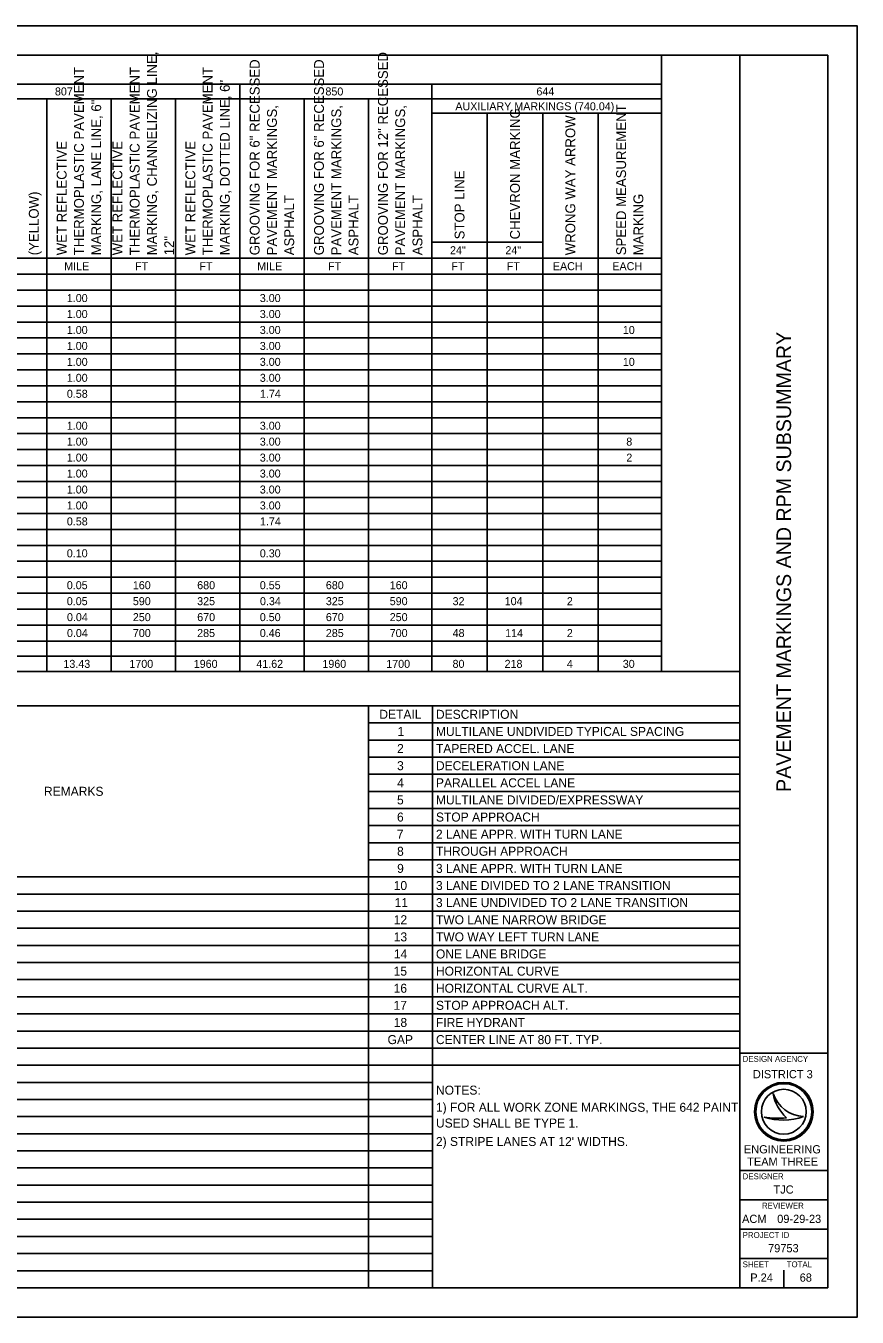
# Model space of a CAD drawing. Extents: x 0 to 34, y 0 to 22.
# Drawn here: x 19.84 to 34, y 0 to 22 of the extents above; entities that cross this region are included whole.
import ezdxf

# ---------------------------------------------------------------- set-up
doc = ezdxf.new("R2010")
doc.units = 0
for name, color, linetype in [('SH_Border', 7, 'Continuous'), ('SH_Cut_Line', 7, 'Continuous'), ('SH_Data', 7, 'Continuous'), ('SH_Text', 7, 'Continuous')]:
    doc.layers.add(name, color=color, linetype=linetype)

msp = doc.modelspace()

# ---------------------------------------------------------------- linework, layer by layer
at = {"layer": 'SH_Border'}
for p, q in [((32, 0.5), (32, 21.5)), ((32, 4.5), (33.5, 4.5)), ((32, 2.5), (33.5, 2.5)), ((32, 2), (33.5, 2)), ((32, 1.5), (33.5, 1.5)), ((32, 1), (33.5, 1))]:
    msp.add_line(p, q, dxfattribs=at)
msp.add_lwpolyline([(1.5, 21.5), (33.5, 21.5), (33.5, 0.5), (1.5, 0.5)], close=True, dxfattribs=at)
at = {"layer": 'SH_Cut_Line'}
msp.add_lwpolyline([(0, 0), (34, 0), (34, 22), (0, 22)], close=True, dxfattribs=at)
at = {"layer": 'SH_Data'}
for p, q in [((32.567, 3.81), (32.567, 3.81)), ((32.417, 3.41), (32.417, 3.41)), ((32.75, 3.5), (32.75, 3.5)), ((33.087, 3.419), (33.087, 3.419)), ((32.375, 0.675), (32.375, 0.675)), ((32.75, 0.5), (32.75, 0.8))]:
    msp.add_line(p, q, dxfattribs=at)
for radius in [0.5, 0.477, 0.477, 0.382]:
    msp.add_circle((32.75, 3.5), radius, dxfattribs=at)
for centre, radius, start, end in [((33.116, 3.998), 0.58, 198.9257, 198.9319), ((33.347, 3.97), 0.796, 191.6379, 191.6421), ((33.116, 3.998), 0.58, 198.9319, 267.1657), ((33.347, 3.97), 0.796, 191.6421, 226.0947), ((32.739, 4.37), 1.013, 251.4576, 290.0832), ((32.648, 4.654), 1.266, 259.4964, 259.4995), ((32.739, 4.37), 1.013, 251.4527, 251.4576), ((32.648, 4.654), 1.266, 259.4995, 276.6672)]:
    msp.add_arc(centre, radius, start, end, dxfattribs=at)
at = {"layer": 'SH_Text'}
for p, q in [((2.835, 21.5), (30.668, 21.5)), ((30.668, 21.5), (30.668, 11)), ((2.835, 21.006), (30.668, 21.006)), ((23.485, 21.006), (23.485, 11)), ((26.757, 21.006), (26.757, 11)), ((12.072, 20.759), (30.668, 20.759)), ((20.198, 20.759), (20.198, 11)), ((21.294, 20.759), (21.294, 11)), ((22.389, 20.759), (22.389, 11)), ((24.581, 20.759), (24.581, 11)), ((25.676, 20.759), (25.676, 11)), ((26.757, 20.512), (30.668, 20.512)), ((27.7, 20.512), (27.7, 11)), ((28.644, 20.512), (28.644, 11)), ((29.587, 20.512), (29.587, 11)), ((26.757, 18.313), (28.644, 18.313)), ((9.044, 18.041), (30.668, 18.041)), ((2.835, 17.769), (30.668, 17.769)), ((2.835, 17.498), (30.668, 17.498)), ((2.835, 17.226), (30.668, 17.226)), ((2.835, 16.954), (30.668, 16.954)), ((2.835, 16.682), (30.668, 16.682)), ((2.835, 16.411), (30.668, 16.411)), ((2.835, 16.139), (30.668, 16.139)), ((2.835, 15.867), (30.668, 15.867)), ((2.835, 15.595), (30.668, 15.595)), ((2.835, 15.324), (30.668, 15.324)), ((2.835, 15.052), (30.668, 15.052)), ((2.835, 14.78), (30.668, 14.78)), ((2.835, 14.508), (30.668, 14.508)), ((2.835, 14.236), (30.668, 14.236)), ((2.835, 13.965), (30.668, 13.965)), ((2.835, 13.693), (30.668, 13.693)), ((2.835, 13.421), (30.668, 13.421)), ((2.835, 13.149), (30.668, 13.149)), ((2.835, 12.878), (30.668, 12.878)), ((2.835, 12.606), (30.668, 12.606)), ((2.835, 12.334), (30.668, 12.334)), ((2.835, 12.062), (30.668, 12.062)), ((2.835, 11.791), (30.668, 11.791)), ((2.835, 11.519), (30.668, 11.519)), ((2.835, 11.259), (30.668, 11.259)), ((1.5, 11), (32, 11)), ((2.835, 11), (30.668, 11)), ((32, 11), (32, 0.5)), ((1.5, 10.417), (32, 10.417)), ((25.676, 10.417), (25.676, 0.5)), ((26.767, 10.417), (26.767, 0.5)), ((25.676, 10.125), (32, 10.125)), ((25.676, 9.833), (32, 9.833)), ((25.676, 9.542), (32, 9.542)), ((25.676, 9.25), (32, 9.25)), ((25.676, 8.958), (32, 8.958)), ((25.676, 8.667), (32, 8.667)), ((25.676, 8.375), (32, 8.375)), ((25.676, 8.083), (32, 8.083)), ((25.676, 7.792), (32, 7.792)), ((1.5, 7.5), (25.676, 7.5)), ((25.676, 7.5), (32, 7.5)), ((1.5, 7.208), (32, 7.208)), ((1.5, 6.917), (32, 6.917)), ((1.5, 6.625), (32, 6.625)), ((1.5, 6.333), (32, 6.333)), ((1.5, 6.042), (32, 6.042)), ((1.5, 5.75), (32, 5.75)), ((1.5, 5.458), (32, 5.458)), ((1.5, 5.167), (32, 5.167)), ((1.5, 4.875), (32, 4.875)), ((1.5, 4.583), (32, 4.583)), ((1.5, 4.292), (32, 4.292)), ((1.5, 4), (26.767, 4)), ((1.5, 3.708), (26.767, 3.708)), ((1.5, 3.417), (26.767, 3.417)), ((1.5, 3.125), (26.767, 3.125)), ((1.5, 2.833), (26.767, 2.833)), ((1.5, 2.542), (26.767, 2.542)), ((1.5, 2.25), (26.767, 2.25)), ((1.5, 1.958), (26.767, 1.958)), ((1.5, 1.667), (26.767, 1.667)), ((1.5, 1.375), (26.767, 1.375)), ((1.5, 1.083), (26.767, 1.083)), ((1.5, 0.792), (25.676, 0.792)), ((25.676, 0.792), (26.767, 0.792)), ((1.5, 0.5), (32, 0.5))]:
    msp.add_line(p, q, dxfattribs=at)

# ---------------------------------------------------------------- texts
at = {"layer": 'SH_Data'}
msp.add_text('PAVEMENT MARKINGS AND RPM SUBSUMMARY', height=0.25, rotation=90, dxfattribs=at).set_placement((32.875, 8.948))
for s, height, p in [('DESIGN AGENCY', 0.1, (32.05, 4.35)), ('DISTRICT 3', 0.14, (32.224, 4.07)), ('ENGINEERING', 0.14, (32.071, 2.79)), ('TEAM THREE', 0.14, (32.127, 2.58)), ('DESIGNER', 0.1, (32.05, 2.35)), ('TJC', 0.14, (32.575, 2.105)), ('REVIEWER', 0.1, (32.378, 1.85)), ('ACM', 0.14, (32.04, 1.605)), ('09-29-23', 0.14, (32.638, 1.605)), ('PROJECT ID', 0.1, (32.05, 1.35)), ('79753', 0.14, (32.483, 1.105)), ('SHEET', 0.1, (32.05, 0.85)), ('TOTAL', 0.1, (32.8, 0.85)), ('P.24', 0.14, (32.179, 0.605)), ('68', 0.14, (33.021, 0.605))]:
    msp.add_text(s, height=height, dxfattribs=at).set_placement(p)
at = {"layer": 'SH_Text'}
for s, p in [('MARKING, CHANNELIZING LINE, ', (22.073, 18.091)), ('GROOVING FOR 6" RECESSED ', (23.823, 18.091)), ('GROOVING FOR 6" RECESSED ', (24.918, 18.091)), ('GROOVING FOR 12" RECESSED ', (26.007, 18.091)), ('THERMOPLASTIC PAVEMENT ', (20.83, 18.091)), ('THERMOPLASTIC PAVEMENT ', (21.779, 18.091)), ('THERMOPLASTIC PAVEMENT ', (23.021, 18.091)), ('MARKING, DOTTED LINE, 6"', (23.315, 18.091)), ('MARKING, LANE LINE, 6"', (21.124, 18.091)), ('PAVEMENT MARKINGS, ', (24.117, 18.091)), ('PAVEMENT MARKINGS, ', (25.212, 18.091)), ('PAVEMENT MARKINGS, ', (26.301, 18.091)), ('CHEVRON MARKING', (28.256, 18.362)), ('WRONG WAY ARROW', (29.199, 18.091)), ('SPEED MEASUREMENT ', (30.064, 18.091)), ('WET REFLECTIVE ', (20.536, 18.091)), ('WET REFLECTIVE ', (21.485, 18.091)), ('WET REFLECTIVE ', (22.727, 18.091)), ('STOP LINE', (27.312, 18.362)), ('(YELLOW)', (20.061, 18.091)), ('ASPHALT', (24.411, 18.091)), ('ASPHALT', (25.506, 18.091)), ('ASPHALT', (26.595, 18.091)), ('MARKING', (30.358, 18.091)), ('12"', (22.367, 18.091))]:
    msp.add_text(s, height=0.168, rotation=90, dxfattribs=at).set_placement(p)
for s, height, p in [('807', 0.1364, (20.337, 20.814)), ('850', 0.1364, (24.944, 20.814)), ('644', 0.1364, (28.537, 20.814)), ('AUXILIARY MARKINGS (740.04)', 0.13638, (27.157, 20.561)), ('24"', 0.1364, (27.066, 18.109)), ('24"', 0.1364, (28.009, 18.109)), ('MILE', 0.1364, (20.495, 17.837)), ('FT', 0.1364, (21.702, 17.837)), ('FT', 0.1364, (22.798, 17.837)), ('MILE', 0.1364, (23.782, 17.837)), ('FT', 0.1364, (24.989, 17.837)), ('FT', 0.1364, (26.077, 17.837)), ('FT', 0.1364, (27.089, 17.837)), ('FT', 0.1364, (28.032, 17.837)), ('EACH', 0.1364, (28.818, 17.837)), ('EACH', 0.1364, (29.83, 17.837)), ('1.00', 0.1364, (20.539, 17.294)), ('3.00', 0.1364, (23.826, 17.294)), ('1.00', 0.1364, (20.539, 17.022)), ('3.00', 0.1364, (23.826, 17.022)), ('1.00', 0.1364, (20.539, 16.75)), ('3.00', 0.1364, (23.826, 16.75)), ('10', 0.1364, (30.009, 16.75)), ('1.00', 0.1364, (20.539, 16.478)), ('3.00', 0.1364, (23.826, 16.478)), ('1.00', 0.1364, (20.539, 16.207)), ('3.00', 0.1364, (23.826, 16.207)), ('10', 0.1364, (30.009, 16.207)), ('1.00', 0.1364, (20.539, 15.935)), ('3.00', 0.1364, (23.826, 15.935)), ('0.58', 0.1364, (20.54, 15.663)), ('1.74', 0.1364, (23.829, 15.663)), ('1.00', 0.1364, (20.539, 15.119)), ('3.00', 0.1364, (23.826, 15.119)), ('1.00', 0.1364, (20.539, 14.848)), ('3.00', 0.1364, (23.826, 14.848)), ('8', 0.136, (30.068, 14.848)), ('1.00', 0.1364, (20.539, 14.576)), ('3.00', 0.1364, (23.826, 14.576)), ('2', 0.136, (30.068, 14.576)), ('1.00', 0.1364, (20.539, 14.304)), ('3.00', 0.1364, (23.826, 14.304)), ('1.00', 0.1364, (20.539, 14.032)), ('3.00', 0.1364, (23.826, 14.032)), ('1.00', 0.1364, (20.539, 13.761)), ('3.00', 0.1364, (23.826, 13.761)), ('0.58', 0.1364, (20.54, 13.489)), ('1.74', 0.1364, (23.829, 13.489)), ('0.10', 0.1364, (20.539, 12.945)), ('0.30', 0.1364, (23.826, 12.945)), ('0.05', 0.1364, (20.539, 12.402)), ('160', 0.1364, (21.664, 12.402)), ('680', 0.1364, (22.76, 12.402)), ('0.55', 0.1364, (23.826, 12.402)), ('680', 0.1364, (24.951, 12.402)), ('160', 0.1364, (26.039, 12.402)), ('0.05', 0.1364, (20.539, 12.13)), ('590', 0.1364, (21.664, 12.13)), ('325', 0.1364, (22.759, 12.13)), ('0.34', 0.1364, (23.829, 12.13)), ('325', 0.1364, (24.951, 12.13)), ('590', 0.1364, (26.039, 12.13)), ('32', 0.1364, (27.11, 12.13)), ('104', 0.1364, (27.997, 12.13)), ('2', 0.136, (29.056, 12.13)), ('0.04', 0.1364, (20.542, 11.858)), ('250', 0.1364, (21.664, 11.858)), ('670', 0.1364, (22.76, 11.858)), ('0.50', 0.1364, (23.826, 11.858)), ('670', 0.1364, (24.951, 11.858)), ('250', 0.1364, (26.039, 11.858)), ('0.04', 0.1364, (20.542, 11.587)), ('700', 0.1364, (21.664, 11.587)), ('285', 0.1364, (22.759, 11.587)), ('0.46', 0.1364, (23.826, 11.587)), ('285', 0.1364, (24.951, 11.587)), ('700', 0.1364, (26.039, 11.587)), ('48', 0.1364, (27.11, 11.587)), ('114', 0.1364, (28.005, 11.587)), ('2', 0.136, (29.056, 11.587)), ('13.43', 0.1364, (20.481, 11.062)), ('1700', 0.1364, (21.605, 11.062)), ('1960', 0.1364, (22.701, 11.062)), ('41.62', 0.1364, (23.767, 11.062)), ('1960', 0.1364, (24.892, 11.062)), ('1700', 0.1364, (25.98, 11.062)), ('80', 0.1364, (27.109, 11.062)), ('218', 0.1364, (27.995, 11.062)), ('4', 0.136, (29.056, 11.062)), ('30', 0.1364, (30.008, 11.062)), ('DETAIL', 0.1533, (25.862, 10.194)), ('DESCRIPTION', 0.15333, (26.826, 10.194)), ('1', 0.153, (26.172, 9.902)), ('MULTILANE UNDIVIDED TYPICAL SPACING', 0.15333, (26.826, 9.902)), ('2', 0.153, (26.164, 9.611)), ('TAPERED ACCEL. LANE', 0.15333, (26.826, 9.611)), ('3', 0.153, (26.164, 9.319)), ('DECELERATION LANE', 0.15333, (26.826, 9.319)), ('REMARKS', 0.1533, (20.15, 8.882)), ('4', 0.153, (26.166, 9.027)), ('PARALLEL ACCEL LANE', 0.15333, (26.826, 9.027)), ('5', 0.153, (26.163, 8.736)), ('MULTILANE DIVIDED/EXPRESSWAY', 0.15333, (26.826, 8.736)), ('6', 0.153, (26.163, 8.444)), ('STOP APPROACH', 0.15333, (26.826, 8.444)), ('7', 0.153, (26.16, 8.152)), ('2 LANE APPR. WITH TURN LANE', 0.15333, (26.826, 8.152)), ('8', 0.153, (26.164, 7.861)), ('THROUGH APPROACH', 0.15333, (26.826, 7.861)), ('9', 0.153, (26.165, 7.569)), ('3 LANE APPR. WITH TURN LANE', 0.15333, (26.826, 7.569)), ('10', 0.1533, (26.107, 7.277)), ('3 LANE DIVIDED TO 2 LANE TRANSITION', 0.15333, (26.826, 7.277)), ('11', 0.1533, (26.123, 6.986)), ('3 LANE UNDIVIDED TO 2 LANE TRANSITION', 0.15333, (26.826, 6.986)), ('12', 0.1533, (26.107, 6.694)), ('TWO LANE NARROW BRIDGE', 0.15333, (26.826, 6.694)), ('13', 0.1533, (26.107, 6.402)), ('TWO WAY LEFT TURN LANE', 0.15333, (26.826, 6.402)), ('14', 0.1533, (26.109, 6.111)), ('ONE LANE BRIDGE', 0.15333, (26.826, 6.111)), ('15', 0.1533, (26.106, 5.819)), ('HORIZONTAL CURVE', 0.15333, (26.826, 5.819)), ('16', 0.1533, (26.106, 5.527)), ('HORIZONTAL CURVE ALT.', 0.15333, (26.826, 5.527)), ('17', 0.1533, (26.104, 5.236)), ('STOP APPROACH ALT.', 0.15333, (26.826, 5.236)), ('18', 0.1533, (26.107, 4.944)), ('FIRE HYDRANT', 0.15333, (26.826, 4.944)), ('GAP', 0.1533, (26.002, 4.652)), ('CENTER LINE AT 80 FT. TYP.', 0.15333, (26.826, 4.652)), ('NOTES:', 0.1533, (26.826, 3.791)), ('1) FOR ALL WORK ZONE MARKINGS, THE 642 PAINT ', 0.15333, (26.826, 3.499)), ('USED SHALL BE TYPE 1.', 0.15333, (26.826, 3.231)), ("2) STRIPE LANES AT 12' WIDTHS.", 0.15333, (26.826, 2.916))]:
    msp.add_text(s, height=height, dxfattribs=at).set_placement(p)

doc.saveas('drawing.dxf')
